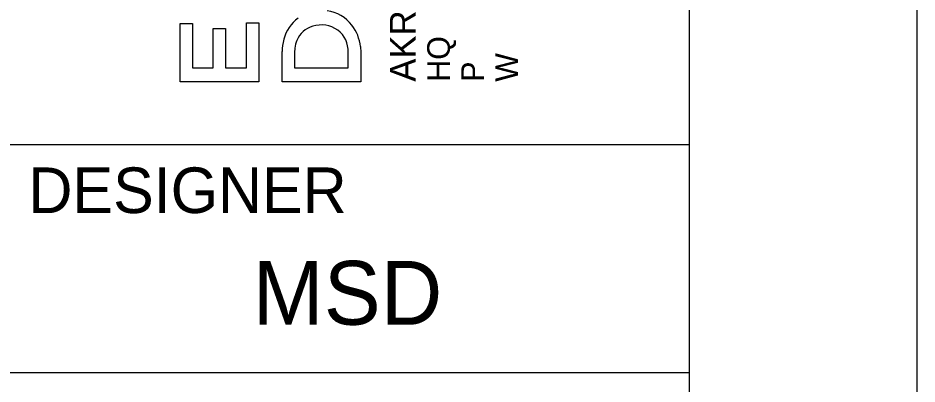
# Model space of a CAD drawing. Extents: x -0.2 to 34, y 0 to 22.
# Drawn here: x 32.027 to 34, y 2.475 to 3.278 of the extents above; entities that cross this region are included whole.
import ezdxf

# ---------------------------------------------------------------- set-up
doc = ezdxf.new("R2010")
doc.units = 0
for name, color, linetype in [('_CIVIL_CONSTRUCTION', 7, 'Continuous'), ('RW_X_CL', 7, 'Continuous'), ('RW_X_Esmt_SH', 7, 'Continuous')]:
    doc.layers.add(name, color=color, linetype=linetype)

msp = doc.modelspace()

# ---------------------------------------------------------------- linework, layer by layer
at = {"layer": '_CIVIL_CONSTRUCTION'}
msp.add_lwpolyline([(0, 0), (34, 0), (34, 22), (0, 22)], close=True, dxfattribs=at)
at = {"layer": 'RW_X_CL'}
for p, q in [((32, 3), (33.5, 3)), ((32, 2.5), (33.5, 2.5))]:
    msp.add_line(p, q, dxfattribs=at)
msp.add_lwpolyline([(1.5, 21.5), (33.5, 21.5), (33.5, 0.5), (1.5, 0.5)], close=True, dxfattribs=at)
at = {"layer": 'RW_X_Esmt_SH'}
for p, q in [((32.383, 3.1379), (32.383, 3.266)), ((32.383, 3.266), (32.4101, 3.266)), ((32.4101, 3.266), (32.4101, 3.1683)), ((32.5286, 3.1683), (32.5286, 3.2672)), ((32.5286, 3.2672), (32.5557, 3.2672)), ((32.5557, 3.2672), (32.5557, 3.1379)), ((32.455, 3.1683), (32.455, 3.2549)), ((32.455, 3.2549), (32.4822, 3.2549)), ((32.4822, 3.2549), (32.4822, 3.1683)), ((32.6064, 3.138), (32.6064, 3.204)), ((32.6347, 3.2118), (32.6341, 3.2023)), ((32.6341, 3.2023), (32.6341, 3.1684)), ((32.7515, 3.1683), (32.7515, 3.2024)), ((32.7785, 3.215), (32.7792, 3.2021)), ((32.7792, 3.2021), (32.7792, 3.138)), ((32.4101, 3.1683), (32.455, 3.1683)), ((32.4822, 3.1683), (32.5286, 3.1683)), ((32.6341, 3.1684), (32.7515, 3.1683)), ((32.5557, 3.1379), (32.383, 3.1379)), ((32.7792, 3.138), (32.6064, 3.138))]:
    msp.add_line(p, q, dxfattribs=at)
msp.add_lwpolyline([(32.383, 3.1379), (32.383, 3.266), (32.4101, 3.266), (32.4101, 3.1683), (32.455, 3.1683), (32.455, 3.2549), (32.4822, 3.2549), (32.4822, 3.1683), (32.5286, 3.1683), (32.5286, 3.2672), (32.5557, 3.2672), (32.5557, 3.1379)], close=True, dxfattribs=at)
for points in [[(32.7785, 3.215), (32.7792, 3.2021), (32.7792, 3.138), (32.6064, 3.138)], [(32.6064, 3.138), (32.6064, 3.204)], [(32.6347, 3.2118), (32.6341, 3.2023), (32.6341, 3.1684), (32.7515, 3.1683), (32.7515, 3.2024)]]:
    msp.add_lwpolyline(points, dxfattribs=at)
for centre, radius, start, end in [((32.6939, 3.2089), 0.0865, 127.2362, 165.148), ((32.6939, 3.2089), 0.0865, 127.2362, 165.148), ((32.6946, 3.2113), 0.0827, 37.8521, 82.402), ((32.6946, 3.2113), 0.0827, 37.8521, 82.402), ((32.6889, 3.2078), 0.054, 106.1881, 157.3861), ((32.6889, 3.2078), 0.054, 106.1881, 157.3861), ((32.6928, 3.1986), 0.0639, 55.6727, 107.2093), ((32.6928, 3.1986), 0.0639, 55.6727, 107.2093), ((32.6859, 3.2057), 0.0931, 5.7333, 37.304), ((32.6859, 3.2057), 0.0931, 5.7333, 37.304), ((32.6929, 3.205), 0.0587, 357.4662, 52.2665), ((32.6929, 3.205), 0.0587, 357.4662, 52.2665), ((32.7143, 3.2028), 0.1078, 164.7861, 179.3704), ((32.7143, 3.2028), 0.1078, 164.7861, 179.3704), ((32.6983, 3.2039), 0.0641, 157.3571, 172.9275), ((32.6983, 3.2039), 0.0641, 157.3571, 172.9275)]:
    msp.add_arc(centre, radius, start, end, dxfattribs=at)

# ---------------------------------------------------------------- texts
for s, height, p in [('AKRON / CLEVELAND / COLUMBUS', 0.056969, (32.9001, 3.138)), ('HQ ', 0.04985, (32.9749, 3.138)), ('W', 0.0498, (33.1244, 3.138)), ('P', 0.0498, (33.0497, 3.138))]:
    msp.add_text(s, height=height, rotation=90, dxfattribs=at).set_placement(p)
for s, height, p in [('DESIGNER', 0.1, (32.05, 2.85)), ('MSD', 0.14, (32.5422, 2.605))]:
    msp.add_text(s, height=height, dxfattribs=at).set_placement(p)

doc.saveas('drawing.dxf')
